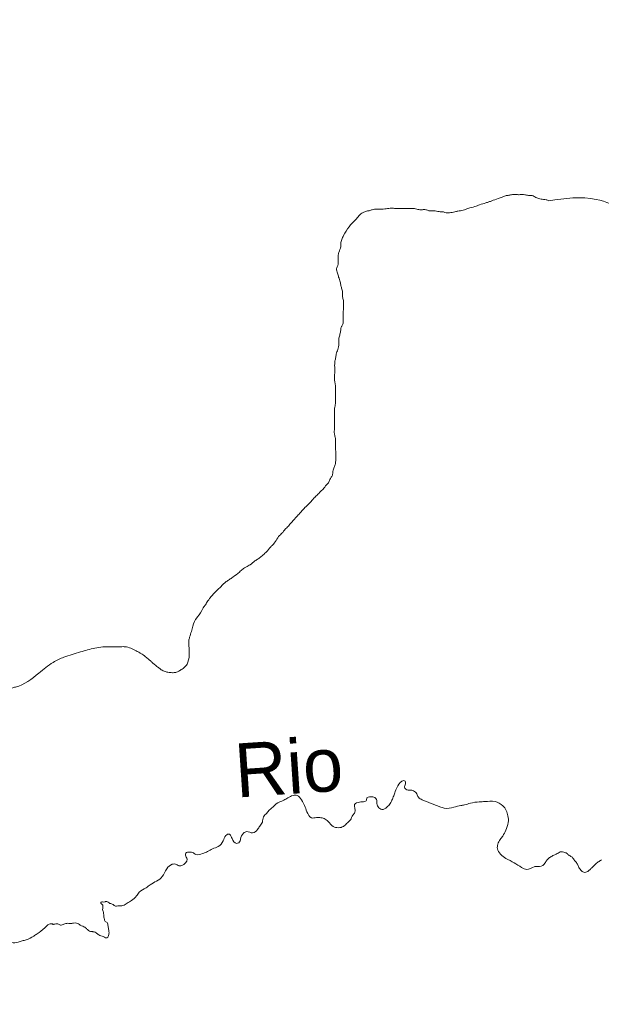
# Model space of a CAD drawing. Extents: x 854879 to 917879, y 8541948 to 8631048.
# Drawn here: x 876542 to 880862, y 8605457 to 8612715 of the extents above; entities that cross this region are included whole.
import ezdxf

# ---------------------------------------------------------------- set-up
doc = ezdxf.new("R2010")
doc.units = 0
doc.header["$LTSCALE"] = 160
for name, color, linetype, lineweight in [('1', 7, 'Continuous', 13), ('12', 7, 'Continuous', 13), ('3', 7, 'Continuous', 13), ('53', 7, 'Continuous', 13)]:
    doc.layers.add(name, color=color, linetype=linetype, lineweight=lineweight)

msp = doc.modelspace()

# ---------------------------------------------------------------- linework, layer by layer
at = {"layer": '12'}
for points in [[(883458.2, 8611696.1), (883312.8, 8611690.2), (883254.5, 8611718.9), (883130.1, 8612194.4), (883075.4, 8612309.7), (882992.8, 8612435.6), (882922.5, 8612525.6), (882806.7, 8612646.7), (882682.3, 8612696.7), (882478.6, 8612709.3), (882317.4, 8612665.3), (882183, 8612509), (882088.6, 8612290.9), (882014.9, 8612093.1), (881954.6, 8611953.6), (881858.8, 8611827.3), (881770.9, 8611726.5), (881683.5, 8611663.8), (881605.9, 8611573), (881515, 8611428.8), (881452.8, 8611342.9), (881245.3, 8611256.2), (880823.3, 8611380.8), (880472, 8611369.8)], [(883458.2, 8611696.1), (883312.8, 8611690.2), (883254.5, 8611718.9), (883130.1, 8612194.4), (883075.4, 8612309.7), (882992.8, 8612435.6), (882922.5, 8612525.6), (882806.7, 8612646.7), (882682.3, 8612696.7), (882478.6, 8612709.3), (882317.4, 8612665.3), (882183, 8612509), (882088.6, 8612290.9), (882014.9, 8612093.1), (881954.6, 8611953.6), (881858.8, 8611827.3), (881770.9, 8611726.5), (881683.5, 8611663.8), (881605.9, 8611573), (881515, 8611428.8), (881452.8, 8611342.9), (881245.3, 8611256.2), (880823.3, 8611380.8), (880472, 8611369.8)], [(880472, 8611369.8), (880451.7, 8611377.7), (880431.4, 8611380.5), (880395.8, 8611386), (880368, 8611399.1), (880340.2, 8611409.6), (880319.8, 8611409.8), (880291.9, 8611415.2), (880258.8, 8611415.6), (880230.8, 8611415.9), (880200.3, 8611416.3), (880174.8, 8611411.4), (880149.3, 8611406.6), (880123.8, 8611396.7), (880095.6, 8611386.8), (880047.1, 8611369.5), (880026.7, 8611362.1), (880003.7, 8611354.7), (879957.7, 8611339.9), (879921.9, 8611327.6), (879870.8, 8611312.9), (879835.1, 8611300.5), (879796.8, 8611293.3), (879773.9, 8611288.5), (879733.1, 8611281.3), (879710.2, 8611281.5), (879689.9, 8611286.9), (879656.9, 8611289.8), (879616.2, 8611295.3), (879580.6, 8611295.8), (879557.8, 8611303.7), (879532.4, 8611303.9), (879506.9, 8611304.2), (879474, 8611312.2), (879438.3, 8611312.7), (879410.4, 8611313), (879367.1, 8611313.4), (879326.4, 8611313.9), (879293.3, 8611314.3), (879252.6, 8611309.6), (879211.8, 8611307.6), (879166, 8611305.5), (879143, 8611298.1), (879117.5, 8611293.3), (879092, 8611283.4), (879061.1, 8611258.2), (879037.9, 8611230.5), (879009.6, 8611202.7), (878988.9, 8611177.5), (878947.4, 8611111.6), (878934.3, 8611083.7), (878926.3, 8611053.2), (878926.1, 8611030.3), (878912.8, 8610987.1), (878907.4, 8610961.7), (878907, 8610928.5), (878904, 8610890.3), (878896.1, 8610867.4), (878903.3, 8610831.7), (878910.6, 8610803.5), (878922.8, 8610767.7), (878927.6, 8610739.6), (878934.9, 8610714), (878939.6, 8610683.4), (878939.3, 8610657.9), (878946.6, 8610629.7), (878946.4, 8610609.3), (878946.1, 8610586.4), (878945.6, 8610550.7), (878945.3, 8610520.1), (878944.9, 8610487), (878941.9, 8610453.8), (878931.5, 8610436.1), (878926.1, 8610410.7), (878920.7, 8610380.2), (878912.7, 8610349.6), (878912.2, 8610308.8), (878904, 8610265.6), (878893.4, 8610232.6), (878888, 8610202), (878882.5, 8610174), (878881.9, 8610120.5), (878881.5, 8610092.5), (878880.8, 8610036.4), (878885.6, 8610008.3), (878887.9, 8609987.8), (878887.5, 8609952.2), (878887.2, 8609929.2), (878886.8, 8609901.2), (878886.4, 8609865.5), (878880.9, 8609829.8)], [(880472, 8611369.8), (880451.7, 8611377.7), (880431.4, 8611380.5), (880395.8, 8611386), (880368, 8611399.1), (880340.2, 8611409.6), (880319.8, 8611409.8), (880291.9, 8611415.2), (880258.8, 8611415.6), (880230.8, 8611415.9), (880200.3, 8611416.3), (880174.8, 8611411.4), (880149.3, 8611406.6), (880123.8, 8611396.7), (880095.6, 8611386.8), (880047.1, 8611369.5), (880026.7, 8611362.1), (880003.7, 8611354.7), (879957.7, 8611339.9), (879921.9, 8611327.6), (879870.8, 8611312.9), (879835.1, 8611300.5), (879796.8, 8611293.3), (879773.9, 8611288.5), (879733.1, 8611281.3), (879710.2, 8611281.5), (879689.9, 8611286.9), (879656.9, 8611289.8), (879616.2, 8611295.3), (879580.6, 8611295.8), (879557.8, 8611303.7), (879532.4, 8611303.9), (879506.9, 8611304.2), (879474, 8611312.2), (879438.3, 8611312.7), (879410.4, 8611313), (879367.1, 8611313.4), (879326.4, 8611313.9), (879293.3, 8611314.3), (879252.6, 8611309.6), (879211.8, 8611307.6), (879166, 8611305.5), (879143, 8611298.1), (879117.5, 8611293.3), (879092, 8611283.4), (879061.1, 8611258.2), (879037.9, 8611230.5), (879009.6, 8611202.7), (878988.9, 8611177.5), (878947.4, 8611111.6), (878934.3, 8611083.7), (878926.3, 8611053.2), (878926.1, 8611030.3), (878912.8, 8610987.1), (878907.4, 8610961.7), (878907, 8610928.5), (878904, 8610890.3), (878896.1, 8610867.4), (878903.3, 8610831.7), (878910.6, 8610803.5), (878922.8, 8610767.7), (878927.6, 8610739.6), (878934.9, 8610714), (878939.6, 8610683.4), (878939.3, 8610657.9), (878946.6, 8610629.7), (878946.4, 8610609.3), (878946.1, 8610586.4), (878945.6, 8610550.7), (878945.3, 8610520.1), (878944.9, 8610487), (878941.9, 8610453.8), (878931.5, 8610436.1), (878926.1, 8610410.7), (878920.7, 8610380.2), (878912.7, 8610349.6), (878912.2, 8610308.8), (878904, 8610265.6), (878893.4, 8610232.6), (878888, 8610202), (878882.5, 8610174), (878881.9, 8610120.5), (878881.5, 8610092.5), (878880.8, 8610036.4), (878885.6, 8610008.3), (878887.9, 8609987.8), (878887.5, 8609952.2), (878887.2, 8609929.2), (878886.8, 8609901.2), (878886.4, 8609865.5), (878880.9, 8609829.8)], [(878880.9, 8609829.8), (878880.5, 8609801.8), (878880.2, 8609773.8), (878879.9, 8609753.3), (878879.7, 8609730.4), (878879.3, 8609699.8), (878878.9, 8609669.2), (878878.7, 8609648.8), (878883.4, 8609623.3), (878888.1, 8609590.1), (878887.9, 8609569.7), (878887.4, 8609534), (878889.7, 8609511), (878889.4, 8609490.6), (878889.1, 8609465.1), (878888.8, 8609439.6), (878885.9, 8609411.6), (878875.5, 8609386.2), (878867.4, 8609353.2), (878862, 8609327.7), (878849.1, 8609307.5), (878838.6, 8609282.1), (878820.5, 8609261.9), (878794.7, 8609229.1), (878774.1, 8609208.9), (878756, 8609191.2), (878732.9, 8609168.6), (878717.4, 8609150.9), (878694.2, 8609125.6), (878660.7, 8609092.9), (878637.5, 8609067.6), (878616.9, 8609044.9), (878593.7, 8609019.7), (878575.6, 8608999.5), (878555, 8608976.8), (878531.7, 8608949), (878508.6, 8608926.3), (878495.6, 8608908.6), (878472.5, 8608885.9), (878446.5, 8608847.9), (878418.1, 8608812.6), (878400.1, 8608794.9), (878384.6, 8608774.7), (878364, 8608754.5), (878335.7, 8608729.4), (878312.6, 8608711.8), (878289.5, 8608696.7), (878253.5, 8608669.1), (878222.8, 8608651.6), (878199.7, 8608636.6), (878174, 8608613.9), (878125.2, 8608576.2), (878099.6, 8608558.6), (878076.5, 8608543.6), (878058.5, 8608528.5), (878037.9, 8608508.3), (878017.3, 8608488.2), (877996.7, 8608468), (877973.5, 8608442.8), (877952.8, 8608417.5), (877939.9, 8608399.8), (877921.7, 8608371.9), (877906.2, 8608349.2), (877895.8, 8608328.9), (877851.7, 8608265.6), (877841.3, 8608247.9), (877817.5, 8608174.2), (877804.3, 8608131), (877798.9, 8608105.6), (877798.6, 8608085.2), (877791.8, 8607945), (877776.2, 8607917.2), (877748, 8607894.5), (877724.9, 8607879.5), (877701.9, 8607869.6), (877676.4, 8607867.3), (877643.4, 8607870.2), (877615.5, 8607878.2), (877587.7, 8607893.8), (877567.5, 8607909.3), (877544.8, 8607927.4), (877524.7, 8607945.5), (877507.1, 8607961)], [(877507.1, 8607961), (877484.4, 8607979.1), (877451.7, 8608005), (877434, 8608015.4), (877408.7, 8608028.4), (877325.1, 8608059.9), (877294.6, 8608060.3), (877161.3, 8608058.2), (877101.3, 8608049.7), (876994.1, 8608021.1), (876871.2, 8607982.6), (876791.2, 8607944.1), (876685.4, 8607864.2), (876512.4, 8607760.6), (876484.3, 8607753.2), (876453.7, 8607740.8), (876428.1, 8607728.4), (876397.4, 8607716), (876364.2, 8607708.7), (876320.9, 8607704.1), (876267.4, 8607697), (876193.5, 8607690.2), (876140, 8607685.7), (876119.7, 8607685.9), (876094.3, 8607686.2), (876073.9, 8607686.5), (876048.5, 8607691.8), (876010.5, 8607705), (875985.2, 8607713), (875959.8, 8607718.3), (875934.4, 8607721.2), (875903.9, 8607721.5), (875875.9, 8607719.3), (875837.6, 8607709.5), (875814.6, 8607704.7), (875801.7, 8607687), (875768.5, 8607674.6), (875740.3, 8607662.2), (875722.3, 8607647.1), (875681.4, 8607629.7), (875663.5, 8607619.7), (875637.9, 8607607.2), (875614.7, 8607587.1), (875571.3, 8607569.7), (875532.8, 8607544.7), (875504.6, 8607527.1), (875481.6, 8607517.2), (875453.5, 8607504.8), (875422.7, 8607487.3), (875394.6, 8607474.8), (875356.2, 8607460), (875325.6, 8607450.1), (875302.7, 8607447.8), (875282.2, 8607440.4), (875254.2, 8607438.2), (875223.5, 8607428.3), (875180.3, 8607426.2), (875159.9, 8607426.5), (875134.5, 8607426.8), (875101.4, 8607427.1), (875076, 8607432.5), (875045.6, 8607443.1), (875017.8, 8607453.6), (874987.4, 8607464.1), (874959.5, 8607474.6), (874934.3, 8607492.8), (874906.5, 8607505.8)]]:
    msp.add_spline(points, degree=3, dxfattribs=at)
at = {"layer": '3'}
for points in [[(877938.3, 8606540), (877974.1, 8606560.2), (878017.4, 8606577.7), (878053.3, 8606618.2), (878074, 8606658.9), (878099.5, 8606668.9), (878112.1, 8606651), (878119.6, 8606635.6), (878152.4, 8606599.7), (878180.5, 8606619.9), (878183.1, 8606632.7), (878203.8, 8606675.8), (878229.3, 8606688.4), (878272.5, 8606677.9), (878308.3, 8606703.2), (878326.3, 8606728.5), (878344.3, 8606759), (878352.3, 8606797.2), (878377.9, 8606825), (878398.5, 8606850.4), (878421.5, 8606868.1), (878447.1, 8606893.4), (878503.3, 8606921), (878533.9, 8606938.7), (878572.2, 8606956.2), (878602.7, 8606956), (878635.5, 8606922.7), (878675.5, 8606835.7), (878708.2, 8606789.6), (878746.3, 8606791.9), (878771.8, 8606791.7), (878802.2, 8606783.9), (878832.6, 8606763.3), (878870.4, 8606724.8), (878908.5, 8606716.9), (878946.7, 8606726.8), (878969.7, 8606747), (878997.9, 8606774.9), (879016, 8606810.4), (879031.4, 8606830.7), (879029.4, 8606889.4), (879065.1, 8606907), (879088, 8606909.3), (879116, 8606916.8), (879121.3, 8606937.2), (879139.1, 8606944.7), (879172.2, 8606944.4), (879194.9, 8606918.8), (879194.7, 8606895.9), (879209.7, 8606865.2), (879240.1, 8606852.2), (879260.5, 8606862.3), (879288.7, 8606890.1), (879306.8, 8606920.6), (879319.7, 8606953.6), (879330.2, 8606984.2), (879358.6, 8607040), (879374, 8607057.8), (879399.5, 8607065.2), (879406.9, 8607042.2), (879399.1, 8607016.8), (879426.9, 8606996.2), (879442.1, 8606996.1), (879467.5, 8606990.8), (879490.2, 8606967.8), (879502.7, 8606942.2), (879530.5, 8606924.2), (879662.3, 8606872.3), (879695.3, 8606861.8), (879766.6, 8606869), (879817.5, 8606881.4), (879845.5, 8606886.3), (879888.9, 8606898.7), (879955, 8606908.5), (879995.8, 8606910.8), (880072, 8606910.2), (880130.2, 8606879.2), (880167.8, 8606805.1), (880169.9, 8606754.1), (880151.7, 8606698.1), (880128.5, 8606654.9), (880110.5, 8606629.6), (880092.4, 8606594), (880089.6, 8606560.9), (880112.1, 8606520), (880152.6, 8606489.1), (880213.3, 8606455.5), (880269, 8606422), (880307, 8606406.5), (880363.1, 8606426.5), (880370.8, 8606429)], [(877938.3, 8606540), (877974.1, 8606560.2), (878017.4, 8606577.7), (878053.3, 8606618.2), (878074, 8606658.9), (878099.5, 8606668.9), (878112.1, 8606651), (878119.6, 8606635.6), (878152.4, 8606599.7), (878180.5, 8606619.9), (878183.1, 8606632.7), (878203.8, 8606675.8), (878229.3, 8606688.4), (878272.5, 8606677.9), (878308.3, 8606703.2), (878326.3, 8606728.5), (878344.3, 8606759), (878352.3, 8606797.2), (878377.9, 8606825), (878398.5, 8606850.4), (878421.5, 8606868.1), (878447.1, 8606893.4), (878503.3, 8606921), (878533.9, 8606938.7), (878572.2, 8606956.2), (878602.7, 8606956), (878635.5, 8606922.7), (878675.5, 8606835.7), (878708.2, 8606789.6), (878746.3, 8606791.9), (878771.8, 8606791.7), (878802.2, 8606783.9), (878832.6, 8606763.3), (878870.4, 8606724.8), (878908.5, 8606716.9), (878946.7, 8606726.8), (878969.7, 8606747), (878997.9, 8606774.9), (879016, 8606810.4), (879031.4, 8606830.7), (879029.4, 8606889.4), (879065.1, 8606907), (879088, 8606909.3), (879116, 8606916.8), (879121.3, 8606937.2), (879139.1, 8606944.7), (879172.2, 8606944.4), (879194.9, 8606918.8), (879194.7, 8606895.9), (879209.7, 8606865.2), (879240.1, 8606852.2), (879260.5, 8606862.3), (879288.7, 8606890.1), (879306.8, 8606920.6), (879319.7, 8606953.6), (879330.2, 8606984.2), (879358.6, 8607040), (879374, 8607057.8), (879399.5, 8607065.2), (879406.9, 8607042.2), (879399.1, 8607016.8), (879426.9, 8606996.2), (879442.1, 8606996.1), (879467.5, 8606990.8), (879490.2, 8606967.8), (879502.7, 8606942.2), (879530.5, 8606924.2), (879662.3, 8606872.3), (879695.3, 8606861.8), (879766.6, 8606869), (879817.5, 8606881.4), (879845.5, 8606886.3), (879888.9, 8606898.7), (879955, 8606908.5), (879995.8, 8606910.8), (880072, 8606910.2), (880130.2, 8606879.2), (880167.8, 8606805.1), (880169.9, 8606754.1), (880151.7, 8606698.1), (880128.5, 8606654.9), (880110.5, 8606629.6), (880092.4, 8606594), (880089.6, 8606560.9), (880112.1, 8606520), (880152.6, 8606489.1), (880213.3, 8606455.5), (880269, 8606422), (880307, 8606406.5), (880363.1, 8606426.5), (880370.8, 8606429)], [(877206.2, 8605935.9), (877203.9, 8605956.3), (877199, 8605986.9), (877191.6, 8606012.4), (877181.5, 8606017.6), (877171.5, 8606035.5), (877166.7, 8606071.2), (877164.2, 8606089.1), (877159.3, 8606101.9), (877159.4, 8606117.2), (877159.5, 8606132.5), (877159.6, 8606142.7), (877144.8, 8606160.1), (877147.2, 8606164.6), (877157.2, 8606165.6), (877175, 8606165.5), (877180.1, 8606168), (877200.4, 8606162.8), (877213.1, 8606155), (877235.9, 8606147.2), (877253.6, 8606134.4), (877271.4, 8606136.8), (877309.6, 8606139.1), (877340.2, 8606156.7), (877373.5, 8606176.9), (877409.3, 8606209.8), (877429.9, 8606237.7), (877481, 8606270.4), (877511.7, 8606293.2), (877601.2, 8606353.7), (877634.7, 8606412.1), (877675.6, 8606445), (877706.2, 8606444.8), (877718.8, 8606437), (877746.8, 8606436.8), (877785.3, 8606482.4), (877772.8, 8606513.1), (877775.5, 8606528.4), (877808.6, 8606535.8), (877826.4, 8606533.1), (877851.7, 8606517.7), (877900, 8606525), (877938.3, 8606540)], [(877206.2, 8605935.9), (877203.9, 8605956.3), (877199, 8605986.9), (877191.6, 8606012.4), (877181.5, 8606017.6), (877171.5, 8606035.5), (877166.7, 8606071.2), (877164.2, 8606089.1), (877159.3, 8606101.9), (877159.4, 8606117.2), (877159.5, 8606132.5), (877159.6, 8606142.7), (877144.8, 8606160.1), (877147.2, 8606164.6), (877157.2, 8606165.6), (877175, 8606165.5), (877180.1, 8606168), (877200.4, 8606162.8), (877213.1, 8606155), (877235.9, 8606147.2), (877253.6, 8606134.4), (877271.4, 8606136.8), (877309.6, 8606139.1), (877340.2, 8606156.7), (877373.5, 8606176.9), (877409.3, 8606209.8), (877429.9, 8606237.7), (877481, 8606270.4), (877511.7, 8606293.2), (877601.2, 8606353.7), (877634.7, 8606412.1), (877675.6, 8606445), (877706.2, 8606444.8), (877718.8, 8606437), (877746.8, 8606436.8), (877785.3, 8606482.4), (877772.8, 8606513.1), (877775.5, 8606528.4), (877808.6, 8606535.8), (877826.4, 8606533.1), (877851.7, 8606517.7), (877900, 8606525), (877938.3, 8606540)], [(880371.3, 8606429.1), (880426.5, 8606437), (880445.3, 8606459.2), (880461.5, 8606481.4), (880482.6, 8606498.4), (880508.7, 8606512.6), (880532.1, 8606524.4), (880563.3, 8606538.4), (880583.6, 8606535), (880603.6, 8606526.5), (880623.4, 8606510.4), (880645.8, 8606496.8), (880662.7, 8606473.1), (880679.7, 8606452), (880691.5, 8606428.6), (880708.2, 8606402.4), (880730.5, 8606386.2), (880761.4, 8606392.6), (880780, 8606409.7), (880795.9, 8606424.3), (880814.5, 8606443.9), (880838.3, 8606463.3), (880861.8, 8606477.6)], [(880371.3, 8606429.1), (880426.5, 8606437), (880445.3, 8606459.2), (880461.5, 8606481.4), (880482.6, 8606498.4), (880508.7, 8606512.6), (880532.1, 8606524.4), (880563.3, 8606538.4), (880583.6, 8606535), (880603.6, 8606526.5), (880623.4, 8606510.4), (880645.8, 8606496.8), (880662.7, 8606473.1), (880679.7, 8606452), (880691.5, 8606428.6), (880708.2, 8606402.4), (880730.5, 8606386.2), (880761.4, 8606392.6), (880780, 8606409.7), (880795.9, 8606424.3), (880814.5, 8606443.9), (880838.3, 8606463.3), (880861.8, 8606477.6)], [(876452.3, 8605456.8), (876462.9, 8605502.6), (876453, 8605540.9), (876445.6, 8605569), (876430.7, 8605609.8), (876415.5, 8605625.2), (876398, 8605658.5), (876395.7, 8605691.7), (876401.1, 8605729.8), (876429.3, 8605762.8), (876429.6, 8605788.3), (876416.9, 8605796), (876399.3, 8605826.7), (876427.6, 8605859.7), (876442.9, 8605867.2), (876473.4, 8605867), (876483.6, 8605864.4), (876531.9, 8605866.6), (876562.5, 8605876.6), (876590.5, 8605884), (876646.7, 8605911.7), (876672.2, 8605929.3), (876728.5, 8605972.3), (876761.8, 8606000.1), (876792.3, 8606002.4)], [(876452.3, 8605456.8), (876462.9, 8605502.6), (876453, 8605540.9), (876445.6, 8605569), (876430.7, 8605609.8), (876415.5, 8605625.2), (876398, 8605658.5), (876395.7, 8605691.7), (876401.1, 8605729.8), (876429.3, 8605762.8), (876429.6, 8605788.3), (876416.9, 8605796), (876399.3, 8605826.7), (876427.6, 8605859.7), (876442.9, 8605867.2), (876473.4, 8605867), (876483.6, 8605864.4), (876531.9, 8605866.6), (876562.5, 8605876.6), (876590.5, 8605884), (876646.7, 8605911.7), (876672.2, 8605929.3), (876728.5, 8605972.3), (876761.8, 8606000.1), (876792.3, 8606002.4)], [(876787.2, 8605997.4), (876810.1, 8606002.3), (876822.8, 8606002.2), (876825.4, 8606002.2), (876845.7, 8605994.4), (876850.7, 8605994.4), (876878.8, 8606004.4), (876894.1, 8606006.8), (876906.8, 8606006.8), (876929.7, 8606006.6), (876942.4, 8606009.1), (876965.3, 8606008.9), (876993.1, 8605993.4), (877010.9, 8605985.6), (877038.7, 8605967.6), (877053.8, 8605954.8), (877069, 8605947), (877079.2, 8605946.9), (877086.8, 8605944.3), (877097, 8605944.3), (877109.6, 8605936.5), (877129.8, 8605921.1), (877162.8, 8605908.1), (877180.5, 8605900.4), (877190.7, 8605900.3), (877206, 8605938.4)], [(876787.2, 8605997.4), (876810.1, 8606002.3), (876822.8, 8606002.2), (876825.4, 8606002.2), (876845.7, 8605994.4), (876850.7, 8605994.4), (876878.8, 8606004.4), (876894.1, 8606006.8), (876906.8, 8606006.8), (876929.7, 8606006.6), (876942.4, 8606009.1), (876965.3, 8606008.9), (876993.1, 8605993.4), (877010.9, 8605985.6), (877038.7, 8605967.6), (877053.8, 8605954.8), (877069, 8605947), (877079.2, 8605946.9), (877086.8, 8605944.3), (877097, 8605944.3), (877109.6, 8605936.5), (877129.8, 8605921.1), (877162.8, 8605908.1), (877180.5, 8605900.4), (877190.7, 8605900.3), (877206, 8605938.4)]]:
    msp.add_spline(points, degree=3, dxfattribs=at)
at = {"layer": '53'}
for points in [[(883458.2, 8611696.1), (883312.8, 8611690.2), (883254.5, 8611718.9), (883130.1, 8612194.4), (883075.4, 8612309.7), (882992.8, 8612435.6), (882922.5, 8612525.6), (882806.7, 8612646.7), (882682.3, 8612696.7), (882478.6, 8612709.3), (882317.4, 8612665.3), (882183, 8612509), (882088.6, 8612290.9), (882014.9, 8612093.1), (881954.6, 8611953.6), (881858.8, 8611827.3), (881770.9, 8611726.5), (881683.5, 8611663.8), (881605.9, 8611573), (881515, 8611428.8), (881452.8, 8611342.9), (881245.3, 8611256.2), (880823.3, 8611380.8), (880472, 8611369.8)], [(880472, 8611369.8), (880451.7, 8611377.7), (880431.4, 8611380.5), (880395.8, 8611386), (880368, 8611399.1), (880340.2, 8611409.6), (880319.8, 8611409.8), (880291.9, 8611415.2), (880258.8, 8611415.6), (880230.8, 8611415.9), (880200.3, 8611416.3), (880174.8, 8611411.4), (880149.3, 8611406.6), (880123.8, 8611396.7), (880095.6, 8611386.8), (880047.1, 8611369.5), (880026.7, 8611362.1), (880003.7, 8611354.7), (879957.7, 8611339.9), (879921.9, 8611327.6), (879870.8, 8611312.9), (879835.1, 8611300.5), (879796.8, 8611293.3), (879773.9, 8611288.5), (879733.1, 8611281.3), (879710.2, 8611281.5), (879689.9, 8611286.9), (879656.9, 8611289.8), (879616.2, 8611295.3), (879580.6, 8611295.8), (879557.8, 8611303.7), (879532.4, 8611303.9), (879506.9, 8611304.2), (879474, 8611312.2), (879438.3, 8611312.7), (879410.4, 8611313), (879367.1, 8611313.4), (879326.4, 8611313.9), (879293.3, 8611314.3), (879252.6, 8611309.6), (879211.8, 8611307.6), (879166, 8611305.5), (879143, 8611298.1), (879117.5, 8611293.3), (879092, 8611283.4), (879061.1, 8611258.2), (879037.9, 8611230.5), (879009.6, 8611202.7), (878988.9, 8611177.5), (878947.4, 8611111.6), (878934.3, 8611083.7), (878926.3, 8611053.2), (878926.1, 8611030.3), (878912.8, 8610987.1), (878907.4, 8610961.7), (878907, 8610928.5), (878904, 8610890.3), (878896.1, 8610867.4), (878903.3, 8610831.7), (878910.6, 8610803.5), (878922.8, 8610767.7), (878927.6, 8610739.6), (878934.9, 8610714), (878939.6, 8610683.4), (878939.3, 8610657.9), (878946.6, 8610629.7), (878946.4, 8610609.3), (878946.1, 8610586.4), (878945.6, 8610550.7), (878945.3, 8610520.1), (878944.9, 8610487), (878941.9, 8610453.8), (878931.5, 8610436.1), (878926.1, 8610410.7), (878920.7, 8610380.2), (878912.7, 8610349.6), (878912.2, 8610308.8), (878904, 8610265.6), (878893.4, 8610232.6), (878888, 8610202), (878882.5, 8610174), (878881.9, 8610120.5), (878881.5, 8610092.5), (878880.8, 8610036.4), (878885.6, 8610008.3), (878887.9, 8609987.8), (878887.5, 8609952.2), (878887.2, 8609929.2), (878886.8, 8609901.2), (878886.4, 8609865.5), (878880.9, 8609829.8)], [(878880.9, 8609829.8), (878880.5, 8609801.8), (878880.2, 8609773.8), (878879.9, 8609753.3), (878879.7, 8609730.4), (878879.3, 8609699.8), (878878.9, 8609669.2), (878878.7, 8609648.8), (878883.4, 8609623.3), (878888.1, 8609590.1), (878887.9, 8609569.7), (878887.4, 8609534), (878889.7, 8609511), (878889.4, 8609490.6), (878889.1, 8609465.1), (878888.8, 8609439.6), (878885.9, 8609411.6), (878875.5, 8609386.2), (878867.4, 8609353.2), (878862, 8609327.7), (878849.1, 8609307.5), (878838.6, 8609282.1), (878820.5, 8609261.9), (878794.7, 8609229.1), (878774.1, 8609208.9), (878756, 8609191.2), (878732.9, 8609168.6), (878717.4, 8609150.9), (878694.2, 8609125.6), (878660.7, 8609092.9), (878637.5, 8609067.6), (878616.9, 8609044.9), (878593.7, 8609019.7), (878575.6, 8608999.5), (878555, 8608976.8), (878531.7, 8608949), (878508.6, 8608926.3), (878495.6, 8608908.6), (878472.5, 8608885.9), (878446.5, 8608847.9), (878418.1, 8608812.6), (878400.1, 8608794.9), (878384.6, 8608774.7), (878364, 8608754.5), (878335.7, 8608729.4), (878312.6, 8608711.8), (878289.5, 8608696.7), (878253.5, 8608669.1), (878222.8, 8608651.6), (878199.7, 8608636.6), (878174, 8608613.9), (878125.2, 8608576.2), (878099.6, 8608558.6), (878076.5, 8608543.6), (878058.5, 8608528.5), (878037.9, 8608508.3), (878017.3, 8608488.2), (877996.7, 8608468), (877973.5, 8608442.8), (877952.8, 8608417.5), (877939.9, 8608399.8), (877921.7, 8608371.9), (877906.2, 8608349.2), (877895.8, 8608328.9), (877851.7, 8608265.6), (877841.3, 8608247.9), (877817.5, 8608174.2), (877804.3, 8608131), (877798.9, 8608105.6), (877798.6, 8608085.2), (877791.8, 8607945), (877776.2, 8607917.2), (877748, 8607894.5), (877724.9, 8607879.5), (877701.9, 8607869.6), (877676.4, 8607867.3), (877643.4, 8607870.2), (877615.5, 8607878.2), (877587.7, 8607893.8), (877567.5, 8607909.3), (877544.8, 8607927.4), (877524.7, 8607945.5), (877507.1, 8607961)], [(877507.1, 8607961), (877484.4, 8607979.1), (877451.7, 8608005), (877434, 8608015.4), (877408.7, 8608028.4), (877325.1, 8608059.9), (877294.6, 8608060.3), (877161.3, 8608058.2), (877101.3, 8608049.7), (876994.1, 8608021.1), (876871.2, 8607982.6), (876791.2, 8607944.1), (876685.4, 8607864.2), (876512.4, 8607760.6), (876484.3, 8607753.2), (876453.7, 8607740.8), (876428.1, 8607728.4), (876397.4, 8607716), (876364.2, 8607708.7), (876320.9, 8607704.1), (876267.4, 8607697), (876193.5, 8607690.2), (876140, 8607685.7), (876119.7, 8607685.9), (876094.3, 8607686.2), (876073.9, 8607686.5), (876048.5, 8607691.8), (876010.5, 8607705), (875985.2, 8607713), (875959.8, 8607718.3), (875934.4, 8607721.2), (875903.9, 8607721.5), (875875.9, 8607719.3), (875837.6, 8607709.5), (875814.6, 8607704.7), (875801.7, 8607687), (875768.5, 8607674.6), (875740.3, 8607662.2), (875722.3, 8607647.1), (875681.4, 8607629.7), (875663.5, 8607619.7), (875637.9, 8607607.2), (875614.7, 8607587.1), (875571.3, 8607569.7), (875532.8, 8607544.7), (875504.6, 8607527.1), (875481.6, 8607517.2), (875453.5, 8607504.8), (875422.7, 8607487.3), (875394.6, 8607474.8), (875356.2, 8607460), (875325.6, 8607450.1), (875302.7, 8607447.8), (875282.2, 8607440.4), (875254.2, 8607438.2), (875223.5, 8607428.3), (875180.3, 8607426.2), (875159.9, 8607426.5), (875134.5, 8607426.8), (875101.4, 8607427.1), (875076, 8607432.5), (875045.6, 8607443.1), (875017.8, 8607453.6), (874987.4, 8607464.1), (874959.5, 8607474.6), (874934.3, 8607492.8), (874906.5, 8607505.8)]]:
    msp.add_spline(points, degree=3, dxfattribs=at)

# ---------------------------------------------------------------- texts
at = {"layer": '1'}
msp.add_text('Rio', height=400, rotation=3.854, dxfattribs=at).set_placement((878153.2, 8606940.2))

doc.saveas('drawing.dxf')
